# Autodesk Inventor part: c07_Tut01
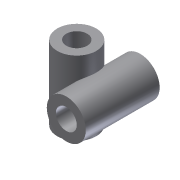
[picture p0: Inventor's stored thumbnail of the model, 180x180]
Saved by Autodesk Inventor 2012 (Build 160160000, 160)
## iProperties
Created: 2011-09
Part Number: c07_Tut01
Material: Default
Document SubType Name: Modeling
Designer: CADCIM
Density: 1 g/cm^3
Author: CADCIM
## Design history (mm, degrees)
sketch "Sketch1"
  geometry: 1 further point
sketch "Sketch2"
  geometry: C1 r 28 at (0, 0); 1 further point
  constraints: 1 centre point, 1 coincident
  dimensions: "d0" = 56 diameter of C1
extrude "Extrusion1" new body sketch "Sketch2" stored distance "d2" = 106; taper "d3" = 0 deg
sketch "Sketch3"
  geometry: L1 (0, 0)-(-83.516, 0); C1 r 28 at (-38, 0)
  constraints: 2 end point, 1 centre point, 1 horizontal, 1 point on line
  dimensions: "d4" = 56 diameter of C1; "d5" = 38 distance of L1.start C1.centre
extrude "Extrusion2" join sketch "Sketch3" stored distance "d7" = 106; taper "d8" = 0 deg
sketch "Sketch5"
  geometry: C1 r 28 at (0, 0) reference; C2 r 15 at (0, 0)
  constraints: 1 centre point, 1 coincident
  dimensions: "d12" = 30 diameter of C2
extrude "Extrusion4" cut sketch "Sketch5" stored distance "d13" = 106; taper "d14" = 0 deg
sketch "Sketch4"
  geometry: C1 r 28 at (0, 0) reference; C2 r 15 at (0, 0); 1 further point
  constraints: 1 centre point, 1 coincident
  dimensions: "d9" = 30 diameter of C2
extrude "Extrusion3" cut sketch "Sketch4" stored distance "d10" = 106; taper "d11" = 0 deg
body "Solid1"
